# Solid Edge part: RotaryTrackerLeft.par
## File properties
Author: wojci
Template: ISO Metric Part.par
Last saved by: wojci
Revision: 25
Application: Solid Edge
Username: wojci
Accuracy: 0.990
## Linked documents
RotaryTracker.par
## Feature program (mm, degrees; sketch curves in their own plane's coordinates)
part copy "LeftBase"
sketch for "unnamed Cutout 1" plane through (4.25, 0, 4) normal (0, -1, 0) x-axis (1, 0, 0)
  line (18.3354, 8) -> (4.25, 8)
  line (4.25, 8) -> (4.8187, 1.5)
  line (4.8187, 1.5) -> (18.3354, 1.5)
  line (18.3354, 1.5) -> (18.3354, 8)
extrude "unnamed Cutout 1" cut through along +normal
sketch for "unnamed Cutout 2" plane through (0, 0, 0) normal (-1, 0, 0) x-axis (0, -1, 0)
  line (8, 12) -> (8.5687, 5.5)
  line (8.5687, 5.5) -> (17.9696, 5.5)
  line (17.9696, 5.5) -> (17.9696, 12)
  line (17.9696, 12) -> (8, 12)
  dimension (linear) = 17.9696
extrude "unnamed Cutout 2" cut through along -normal
chamfer "unnamed Chamfer 1"
fillet "Round_1" radius 10
fillet "Round_3" radius 7
chamfer "Chamfer_3" setback 1.5
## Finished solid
Body 1: solid body, 29 faces, 69 edges, 41 vertices.
  Faces by surface: plane 14, cylinder 9, spline 3, swept 2, blend 1
  Edges by curve: line 30, circle 16, curve on surface 11, spline 6, intersection 5, ellipse 1
Bounding box of the edges (mm; curved faces can reach further): 31.084 x 45.394 x 12.000, from (-8.5, -13.7771, 0) to (22.5835, 31.6168, 12).
Cylindrical faces by radius (mm): R1.35 x2, R1.8 x1, R2.75 x2, R6.25 x2, R7 x1, R8.5 x1
Planar faces by outward normal: +x 2, +z 3, -x 3, -z 2, oblique 4
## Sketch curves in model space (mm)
line (8.5, 0, 12) -> (8.5, 0, 0)
line (9.0687, 0, 5.5) -> (22.5854, 0, 5.5)
line (22.5854, 0, 5.5) -> (22.5854, 0, 12)
line (22.5854, 0, 12) -> (8.5, 0, 12)
line (8.5, 0, 12) -> (9.0687, 0, 5.5)
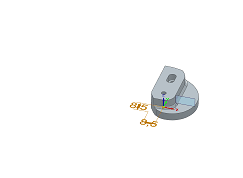
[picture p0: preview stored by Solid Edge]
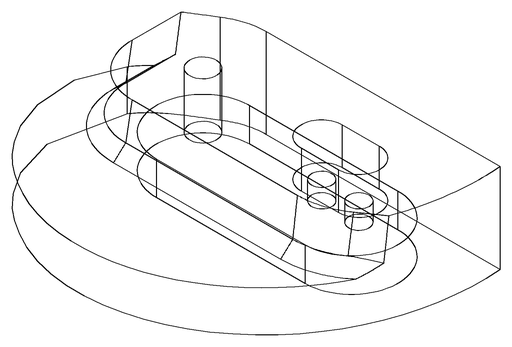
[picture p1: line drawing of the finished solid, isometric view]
